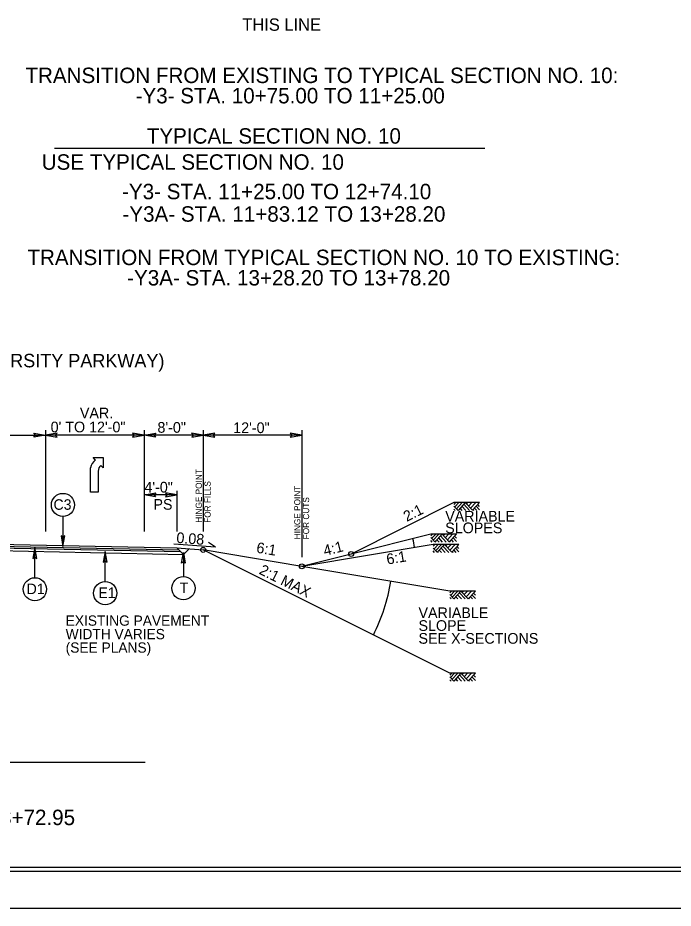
# Model space of a CAD drawing. Extents: x 1904401 to 1905163, y 193929 to 194736.
# Drawn here: x 1904916.2 to 1904996, y 194254.3 to 194362.6 of the extents above; entities that cross this region are included whole.
import ezdxf

# ---------------------------------------------------------------- set-up
doc = ezdxf.new("R2010")
doc.units = 0
for name, color, linetype in [('Old_Level_1', 7, 'Continuous'), ('Old_Level_11', 7, 'Continuous'), ('Old_Level_20', 7, 'Continuous'), ('Prop Lane Arrow CELL', 7, 'Continuous'), ('Sheet Cutting Line CELL', 7, 'Continuous'), ('Sheet Plot Border Inside CELL', 7, 'Continuous'), ('Sheet Plot Border Outside CELL', 7, 'Continuous'), ('Sheet Typical CELL', 7, 'Continuous'), ('Typical Arrow Superelevation CELL', 7, 'Continuous'), ('Typical Hinge Slope Arterial CELL', 7, 'Continuous'), ('Typical Terminator CELL', 7, 'Continuous'), ('Typical Text Centerline CELL', 7, 'Continuous')]:
    doc.layers.add(name, color=color, linetype=linetype)

msp = doc.modelspace()

# ---------------------------------------------------------------- linework, layer by layer
at = {"layer": 'Old_Level_1'}
msp.add_line((1904920.67, 194346.78), (1904973.06, 194346.78), dxfattribs=at)
at = {"layer": 'Old_Level_11'}
for p, q in [((1904921.72, 194301.97), (1904921.72, 194298.31)), ((1904918.3, 194294.54), (1904918.3, 194298.19)), ((1904926.86, 194294.07), (1904926.86, 194297.72)), ((1904936.38, 194297.6), (1904936.38, 194294.66))]:
    msp.add_line(p, q, dxfattribs=at)
for points in [[(1904921.5, 194299.62), (1904921.72, 194298.31), (1904921.95, 194299.63), (1904921.72, 194299.46)], [(1904918.52, 194296.88), (1904918.3, 194298.19), (1904918.07, 194296.88), (1904918.3, 194297.04)], [(1904927.08, 194296.41), (1904926.86, 194297.72), (1904926.63, 194296.41), (1904926.86, 194296.57)], [(1904936.15, 194296.29), (1904936.38, 194297.6), (1904936.61, 194296.28), (1904936.38, 194296.45)]]:
    msp.add_lwpolyline(points, close=True, dxfattribs=at)
for centre in [(1904921.72, 194303.38), (1904918.3, 194293.12), (1904936.38, 194293.25), (1904926.86, 194292.65)]:
    msp.add_circle(centre, 1.41, dxfattribs=at)
at = {"layer": 'Prop Lane Arrow CELL'}
for p, q in [((1904907.59, 194311.86), (1904919.59, 194311.86)), ((1904919.59, 194312.46), (1904919.59, 194300.13)), ((1904931.59, 194311.86), (1904919.59, 194311.86)), ((1904931.59, 194312.46), (1904931.59, 194300.15)), ((1904931.59, 194312.46), (1904931.59, 194300.13)), ((1904950.79, 194311.86), (1904931.59, 194311.86)), ((1904938.79, 194312.46), (1904938.79, 194300.15)), ((1904950.79, 194312.46), (1904950.79, 194297.03)), ((1904925.38, 194309.14), (1904926.62, 194309.15)), ((1904925.68, 194308.84), (1904925.38, 194309.14)), ((1904926.63, 194307.89), (1904926.34, 194308.18)), ((1904926.62, 194309.15), (1904926.63, 194307.89)), ((1904925.09, 194304.92), (1904925.09, 194307.88)), ((1904926.01, 194307.48), (1904926.01, 194304.92)), ((1904935.59, 194305.09), (1904935.59, 194300.15)), ((1904926.01, 194304.92), (1904925.09, 194304.92)), ((1904935.59, 194304.6), (1904931.59, 194304.6)), ((1904969.51, 194303.67), (1904969.31, 194303.45)), ((1904969.8, 194302.71), (1904969.31, 194303.24)), ((1904969.47, 194302.7), (1904969.31, 194302.88)), ((1904969.9, 194303.67), (1904969.4, 194303.14)), ((1904970.3, 194303.67), (1904969.6, 194302.92)), ((1904970.68, 194303.67), (1904969.8, 194302.71)), ((1904969.95, 194302.7), (1904969.87, 194302.79)), ((1904970.31, 194302.7), (1904970.05, 194302.98)), ((1904970.75, 194302.7), (1904970.27, 194303.22)), ((1904971.19, 194302.7), (1904970.49, 194303.46)), ((1904971.56, 194302.73), (1904970.68, 194303.67)), ((1904971, 194303.67), (1904970.84, 194303.5)), ((1904971.48, 194303.67), (1904971.08, 194303.24)), ((1904971.96, 194303.67), (1904971.32, 194302.98)), ((1904972.43, 194303.66), (1904971.56, 194302.73)), ((1904971.71, 194302.7), (1904971.63, 194302.8)), ((1904972.08, 194302.7), (1904971.81, 194303)), ((1904972.43, 194302.78), (1904972.02, 194303.22)), ((1904972.43, 194303.18), (1904972.21, 194303.42)), ((1904966.69, 194299.84), (1904966.49, 194299.62)), ((1904967.08, 194299.84), (1904966.58, 194299.3)), ((1904967.48, 194299.84), (1904966.78, 194299.09)), ((1904967.86, 194299.83), (1904966.98, 194298.88)), ((1904968.37, 194298.87), (1904967.67, 194299.62)), ((1904968.74, 194298.89), (1904967.86, 194299.83)), ((1904968.18, 194299.84), (1904968.02, 194299.66)), ((1904968.66, 194299.84), (1904968.26, 194299.4)), ((1904969.14, 194299.84), (1904968.5, 194299.15)), ((1904969.61, 194299.83), (1904968.74, 194298.89)), ((1904969.61, 194299.34), (1904969.39, 194299.58)), ((1904901.59, 194298.86), (1904935.59, 194298.18)), ((1904966.98, 194298.88), (1904966.49, 194299.4)), ((1904966.65, 194298.87), (1904966.49, 194299.04)), ((1904966.99, 194298.58), (1904966.79, 194298.36)), ((1904967.38, 194298.58), (1904966.88, 194298.04)), ((1904967.13, 194298.87), (1904967.05, 194298.96)), ((1904967.78, 194298.58), (1904967.08, 194297.83)), ((1904967.49, 194298.87), (1904967.23, 194299.15)), ((1904968.16, 194298.58), (1904967.27, 194297.62)), ((1904967.93, 194298.87), (1904967.45, 194299.38)), ((1904969.04, 194297.63), (1904968.16, 194298.58)), ((1904968.48, 194298.58), (1904968.32, 194298.41)), ((1904968.96, 194298.58), (1904968.56, 194298.15)), ((1904969.44, 194298.58), (1904968.8, 194297.89)), ((1904968.89, 194298.87), (1904968.81, 194298.96)), ((1904969.26, 194298.87), (1904968.99, 194299.16)), ((1904969.91, 194298.57), (1904969.04, 194297.63)), ((1904969.61, 194298.95), (1904969.2, 194299.38)), ((1904913.37, 194297.83), (1904936.4, 194297.37)), ((1904913.38, 194298.37), (1904935.85, 194297.92)), ((1904913.38, 194298.16), (1904936.06, 194297.71)), ((1904936.4, 194297.37), (1904935.59, 194298.18)), ((1904935.59, 194298.18), (1904938.79, 194297.91)), ((1904936.4, 194297.37), (1904937.09, 194298.05)), ((1904967.27, 194297.62), (1904966.79, 194298.14)), ((1904966.95, 194297.61), (1904966.79, 194297.78)), ((1904967.43, 194297.61), (1904967.35, 194297.7)), ((1904967.78, 194297.61), (1904967.52, 194297.89)), ((1904968.22, 194297.61), (1904967.74, 194298.13)), ((1904968.67, 194297.61), (1904967.96, 194298.37)), ((1904969.19, 194297.61), (1904969.1, 194297.7)), ((1904969.56, 194297.61), (1904969.29, 194297.9)), ((1904969.91, 194297.69), (1904969.5, 194298.13)), ((1904969.91, 194298.09), (1904969.69, 194298.33)), ((1904968.99, 194292.91), (1904968.79, 194292.69)), ((1904969.27, 194291.96), (1904968.79, 194292.48)), ((1904968.95, 194291.95), (1904968.79, 194292.12)), ((1904969.38, 194292.91), (1904968.88, 194292.38)), ((1904969.78, 194292.91), (1904969.08, 194292.16)), ((1904970.16, 194292.91), (1904969.27, 194291.96)), ((1904969.43, 194291.95), (1904969.35, 194292.03)), ((1904969.78, 194291.95), (1904969.52, 194292.22)), ((1904970.22, 194291.95), (1904969.74, 194292.46)), ((1904970.67, 194291.95), (1904969.96, 194292.7)), ((1904971.04, 194291.97), (1904970.16, 194292.91)), ((1904970.48, 194292.91), (1904970.32, 194292.74)), ((1904970.96, 194292.91), (1904970.56, 194292.48)), ((1904971.44, 194292.91), (1904970.8, 194292.22)), ((1904971.91, 194292.9), (1904971.04, 194291.97)), ((1904971.19, 194291.95), (1904971.1, 194292.04)), ((1904971.56, 194291.95), (1904971.29, 194292.24)), ((1904971.91, 194292.02), (1904971.5, 194292.46)), ((1904971.91, 194292.42), (1904971.69, 194292.66)), ((1904968.99, 194282.91), (1904968.79, 194282.69)), ((1904969.27, 194281.96), (1904968.79, 194282.48)), ((1904969.38, 194282.91), (1904968.88, 194282.38)), ((1904969.78, 194282.91), (1904969.08, 194282.17)), ((1904970.16, 194282.91), (1904969.27, 194281.96)), ((1904969.78, 194281.95), (1904969.52, 194282.23)), ((1904970.22, 194281.95), (1904969.74, 194282.46)), ((1904970.67, 194281.95), (1904969.96, 194282.7)), ((1904971.04, 194281.97), (1904970.16, 194282.91)), ((1904970.48, 194282.91), (1904970.32, 194282.74)), ((1904970.96, 194282.91), (1904970.56, 194282.48)), ((1904971.44, 194282.91), (1904970.8, 194282.23)), ((1904971.91, 194282.9), (1904971.04, 194281.97)), ((1904971.56, 194281.95), (1904971.29, 194282.24)), ((1904971.91, 194282.02), (1904971.5, 194282.46)), ((1904971.91, 194282.42), (1904971.69, 194282.66)), ((1904968.95, 194281.95), (1904968.79, 194282.12)), ((1904969.43, 194281.95), (1904969.35, 194282.04)), ((1904971.19, 194281.95), (1904971.1, 194282.04)), ((1904870.76, 194272.11), (1904931.72, 194272.11))]:
    msp.add_line(p, q, dxfattribs=at)
for points in [[(1904972.43, 194303.67), (1904969.31, 194303.67)], [(1904969.61, 194299.84), (1904966.49, 194299.84)], [(1904969.91, 194298.58), (1904966.79, 194298.58)], [(1904971.91, 194292.91), (1904968.79, 194292.91)], [(1904971.91, 194282.91), (1904968.79, 194282.91)]]:
    msp.add_lwpolyline(points, dxfattribs=at)
for centre, radius, start, end in [((1904926.54, 194307.66), 1.47, 126.0122, 171.3239), ((1904926.93, 194307.49), 0.917, 130.3418, 180)]:
    msp.add_arc(centre, radius, start, end, dxfattribs=at)
at = {"layer": 'Sheet Cutting Line CELL'}
msp.add_line((1904710.69, 194254.34), (1905047.49, 194254.34), dxfattribs=at)
at = {"layer": 'Sheet Plot Border Inside CELL'}
msp.add_lwpolyline([(1905046.59, 194469.85), (1904713.29, 194469.85), (1904713.29, 194258.83), (1905046.59, 194258.83)], close=True, dxfattribs=at)
at = {"layer": 'Sheet Plot Border Outside CELL'}
msp.add_lwpolyline([(1905047.49, 194474.34), (1904710.69, 194474.34), (1904710.69, 194254.34), (1905047.49, 194254.34)], close=True, dxfattribs=at)
at = {"layer": 'Sheet Typical CELL'}
msp.add_lwpolyline([(1905044.09, 194469.34), (1904744.09, 194469.34), (1904744.09, 194259.34), (1905044.09, 194259.34)], close=True, dxfattribs=at)
at = {"layer": 'Typical Arrow Superelevation CELL'}
for q in [(1904935.2, 194298.61), (1904939.45, 194298.8)]:
    msp.add_line((1904940.28, 194298.23), q, dxfattribs=at)
at = {"layer": 'Typical Hinge Slope Arterial CELL'}
for p, q in [((1904969.31, 194303.67), (1904956.79, 194297.41)), ((1904966.49, 194299.84), (1904956.79, 194297.41)), ((1904966.79, 194298.58), (1904950.79, 194295.91)), ((1904950.79, 194295.91), (1904938.79, 194297.91)), ((1904968.79, 194282.91), (1904938.79, 194297.91)), ((1904956.79, 194297.41), (1904950.79, 194295.91)), ((1904968.79, 194292.91), (1904950.79, 194295.91))]:
    msp.add_line(p, q, dxfattribs=at)
for centre in [(1904938.79, 194297.91), (1904956.79, 194297.41), (1904950.79, 194295.91)]:
    msp.add_circle(centre, 0.297, dxfattribs=at)
for centre, radius, start, end in [((1904956.79, 194297.41), 7.74, 5.8103, 14.0363), ((1904938.79, 194297.91), 23.16, 333.435, 350.5376)]:
    msp.add_arc(centre, radius, start, end, dxfattribs=at)
at = {"layer": 'Typical Terminator CELL'}
for points in [[(1904918.19, 194312.11), (1904919.59, 194311.86), (1904918.18, 194311.61), (1904918.36, 194311.86)], [(1904921, 194312.11), (1904919.59, 194311.86), (1904921.01, 194311.61), (1904920.83, 194311.86)], [(1904930.19, 194311.62), (1904931.59, 194311.86), (1904930.18, 194312.11), (1904930.36, 194311.86)], [(1904933, 194311.62), (1904931.59, 194311.86), (1904933.01, 194312.11), (1904932.83, 194311.86)], [(1904937.39, 194311.62), (1904938.79, 194311.86), (1904937.38, 194312.11), (1904937.56, 194311.86)], [(1904940.2, 194312.11), (1904938.79, 194311.86), (1904940.21, 194311.61), (1904940.03, 194311.86)], [(1904949.39, 194311.62), (1904950.79, 194311.86), (1904949.38, 194312.11), (1904949.56, 194311.86)], [(1904933, 194304.35), (1904931.59, 194304.6), (1904933.01, 194304.84), (1904932.83, 194304.6)], [(1904934.19, 194304.35), (1904935.59, 194304.6), (1904934.18, 194304.84), (1904934.36, 194304.6)]]:
    msp.add_lwpolyline(points, close=True, dxfattribs=at)

# ---------------------------------------------------------------- texts
at = {"layer": 'Old_Level_1'}
for s, p in [('TRANSITION FROM EXISTING TO TYPICAL SECTION NO. 10:', (1904917.15, 194354.69)), ('TRANSITION FROM TYPICAL SECTION NO. 10 TO EXISTING:', (1904917.39, 194332.55))]:
    msp.add_text(s, height=1.875, dxfattribs=at).set_placement(p)
at = {"layer": 'Old_Level_20'}
for s, height, p in [('C3', 1.279, (1904920.57, 194302.79)), ('D1', 1.279, (1904917.3, 194292.53)), ('E1', 1.279, (1904926.03, 194292.06)), ('T', 1.28, (1904935.94, 194292.65))]:
    msp.add_text(s, height=height, dxfattribs=at).set_placement(p)
at = {"layer": 'Prop Lane Arrow CELL'}
for s, height, rotation, p in [('THIS LINE', 1.5, 0.0002, (1904943.54, 194361.05)), ('0.08', 1.3, 355.8018, (1904935.49, 194298.77))]:
    msp.add_text(s, height=height, rotation=rotation, dxfattribs=at).set_placement(p)
for s, height, p in [('-Y3- STA. 10+75.00 TO 11+25.00', 1.875, (1904930.56, 194352.22)), ('TYPICAL SECTION NO. 10', 1.875, (1904931.92, 194347.32)), ('USE TYPICAL SECTION NO. 10', 1.875, (1904919.13, 194344.15)), ('-Y3- STA. 11+25.00 TO 12+74.10', 1.875, (1904928.91, 194340.56)), ('-Y3A- STA. 11+83.12 TO 13+28.20', 1.875, (1904928.96, 194337.83)), ('-Y3A- STA. 13+28.20 TO 13+78.20', 1.875, (1904929.53, 194330.07)), ('VAR.', 1.3, (1904923.78, 194313.91)), ('0\' TO 12\'-0"', 1.3, (1904920.22, 194312.21)), ('8\'-0"', 1.3, (1904933.22, 194312.16)), ('12\'-0"', 1.3, (1904942.44, 194312.12)), ('4\'-0"', 1.3, (1904931.63, 194304.89)), ('PS', 1.3, (1904932.73, 194302.8)), ('EXISTING PAVEMENT', 1.25, (1904922.05, 194288.69)), ('WIDTH VARIES', 1.25, (1904922.05, 194287.05)), ('(SEE PLANS)', 1.25, (1904922.05, 194285.41)), ('-Y4- STA. 32+98.24 TO 38+72.95', 1.875, (1904885.56, 194264.44))]:
    msp.add_text(s, height=height, dxfattribs=at).set_placement(p)
at = {"layer": 'Typical Hinge Slope Arterial CELL'}
for s, height, rotation, p in [('HINGE POINT ', 0.75, 90, (1904938.62, 194301.21)), ('FOR FILLS', 0.75, 90, (1904939.69, 194301.21)), ('HINGE POINT ', 0.75, 90, (1904950.61, 194299.2)), ('FOR CUTS', 0.75, 90, (1904951.68, 194299.2)), ('2:1', 1.3, 26.565, (1904963.55, 194301.3)), ('6:1', 1.3, 350.5377, (1904945.19, 194297.59)), ('4:1', 1.3, 14.0362, (1904953.59, 194297.17)), ('6:1', 1.3, 9.4635, (1904961.2, 194296.12)), ('2:1 MAX', 1.3, 333.4349, (1904945.49, 194295.05))]:
    msp.add_text(s, height=height, rotation=rotation, dxfattribs=at).set_placement(p)
for s, p in [('VARIABLE ', (1904968.24, 194301.36)), ('SLOPES', (1904968.24, 194299.94)), ('VARIABLE ', (1904964.99, 194289.62)), ('SLOPE', (1904964.99, 194288.06)), ('SEE X-SECTIONS', (1904964.99, 194286.5))]:
    msp.add_text(s, height=1.3, dxfattribs=at).set_placement(p)
at = {"layer": 'Typical Text Centerline CELL'}
msp.add_text('L -Y4- (UNIVERSITY PARKWAY) ', height=1.6411, rotation=359.9469, dxfattribs=at).set_placement((1904901.27, 194320.13))

doc.saveas('drawing.dxf')
